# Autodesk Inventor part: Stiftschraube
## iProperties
Created: 2006-12
Part Number: Stiftschraube
Document SubType Name: Modeling
Designer: Kumpf
Manufacturer: Standard
Standards Organization: Custom
Author: Kumpf
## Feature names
1. Drehung1 [Revolution]
2. Extrusion1
3. Fase2 [Chamfer]
4. Fase3 [Chamfer]
5. Fase4 [Chamfer]
